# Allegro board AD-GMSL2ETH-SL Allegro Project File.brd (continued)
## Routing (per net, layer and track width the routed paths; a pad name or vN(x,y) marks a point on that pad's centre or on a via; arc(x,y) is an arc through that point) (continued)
UNNAMED_17_ADMAX2520X_I70_COMP: length 2
  TOP w0.254: U10.6 R102.1
UNNAMED_17_ADMAX2520X_I70_CS: length 16.7
  TOP w0.254: v1(28.68,85.22) 28.68,86.2 28.93,86.45 U10.10
  BOTTOM w0.254: R108.2 35.56,74.68 C230.1
  BOTTOM w0.305: v1(28.68,85.22) 28.68,84.05 35.26,77.48 35.26,76.2 35.7,75.76 C230.1
UNNAMED_17_ADMAX2520X_I70_DH: length 13.2
  TOP w0.305: U10.17 33.93,86.95 v2(34.32,86.56)
  TOP w0.406: v2(45.17,85.57) R106.1
  BOTTOM w0.406: v2(45.17,85.57) 44.18,86.56 v2(34.32,86.56)
UNNAMED_17_ADMAX2520X_I70_DL: length 14.8
  TOP w0.305: U10.15 v1(32.2,84.63)
  TOP w0.406: R107.1 v1(38.02,73.79)
  BOTTOM w0.406: v1(38.02,73.79) 38.02,76.71 32.2,82.53 v1(32.2,84.63)
UNNAMED_17_ADMAX2520X_I70_FB: length 3.5
  TOP w0.254: R112.2 R110.1 R237.1 U10.8
UNNAMED_17_ADMAX2520X_I70_FOSC: length 4.2
  TOP w0.254: R99.1 27.42,90.38 30.32,90.38 30.7,90 U10.4
UNNAMED_17_ADMAX2520X_I70_FSYNC: length 3.6
  TOP w0.254: U10.3 31.2,90.18 31.03,90.36 R93.2 R94.1 R95.1
UNNAMED_17_ADMAX2520X_I70_LX: length 14
  BOTTOM w0.508: v1(45.21,81.58) 41.25,85.55 v1(34.42,85.55) 33.57,85.55 C229.2
UNNAMED_17_ADMAX2520X_I70_OUT: length 17.6
  TOP w0.254: U10.9 28.69,86.95 27.94,86.2 v1(27.94,85.22)
  BOTTOM w0.254: R111.2 34.24,74.68 C230.2
  BOTTOM w0.305: v1(27.94,85.22) 27.94,83.75 34.54,77.14 34.54,76.2 34.1,75.76 C230.2
UNNAMED_17_ADMAX2520X_I70_PGOOD: length 3.5
  TOP w0.254: R249.2 27.86,89.48 28.32,89.95 29.95,89.95 30.2,89.7 U10.5
UNNAMED_17_ADMAX2520X_I70_SPS: length 2.6
  TOP w0.254: R96.2 R97.1 32.36,90.34 32.2,90.19 U10.1
UNNAMED_17_ADMAX17573_I106_BST: length 1.6
  TOP w0.305: U21.22 36.23,53.82 C247.2
UNNAMED_17_ADMAX17573_I106_MODE: length 3.6
  TOP w0.305: R241.1 R240.1 40.91,51.1 R239.1 39.59,51.1 39.25,50.76 U21.15
UNNAMED_17_ADMAX17573_I106_RESETN: length 1.8
  TOP w0.305: v1(39.18,50.02) 38.94,50.26 U21.14
  BOTTOM w0.483: R250.2 38.66,50.02 v1(39.18,50.02)
UNNAMED_17_ADMAX17573_I106_RT: length 2.1
  TOP w0.305: R238.1 39.19,53.34 38.61,52.76 U21.19
UNNAMED_17_ADMAX17573_I106_SS: length 2.6
  TOP w0.305: C248.1 39.83,52.2 38.89,51.26 U21.16
UNNAMED_17_CAP_I8_N1: length 11.2
  BOTTOM w0.762: P11.1 13.91,107.35 ; P11.1 13.91,104.55 ; P11.1 15.31,105.95 ; P11.1 12.51,105.95 ; 18.03,105.95 P11.4 ; P11.4 19.42,104.55 ; P11.4 20.82,105.95 ; P11.4 19.42,107.35
UNNAMED_17_CAP_I8_N2: length 11.2
  BOTTOM w0.762: 13.91,112.94 P11.3 ; P11.3 12.51,114.33 ; P11.3 15.31,114.33 ; P11.3 13.91,115.73 ; P11.6 19.42,115.73 ; P11.6 18.03,114.33 ; P11.6 19.42,112.94 ; P11.6 20.82,114.33
UNNAMED_17_CAP_I66_N1: length 0.9
  TOP w0.254: R102.2 24.84,88.45
UNNAMED_17_IND_I90_N2: length 2.2
  TOP w0.254: R109.1 v1(35.56,71.7)
  BOTTOM w0.254: v1(35.56,71.7) R108.1
UNNAMED_17_RES_I48_N2: length 9.6
  TOP w0.559: S12.2 45.44,111.4 R141.2
UNNAMED_17_RES_I79_N2: length 1.7
  TOP w0.406: Q7.4 44.72,83.96 44.27,84.41 R106.2
UNNAMED_17_RES_I83_N2: length 1.8
  TOP w0.406: R107.2 38.89,72.27 39.23,72.61 Q5.4
USB_DEBUG_N: length 6.1
  BOTTOM w0.127: U23.7 81.56,9.32 81.73,9.15 81.73,7.6 81.55,7.43 D4.C 81.55,6.85 81.71,6.69 81.71,5.06 81.55,4.9 P10.2
USB_DEBUG_P: length 6.1
  BOTTOM w0.127: U23.6 82.21,9.31 82.05,9.15 82.05,7.59 82.21,7.43 D5.C 82.21,6.85 82.04,6.67 82.04,5.06 82.2,4.9 P10.3
VCAM_9V0: length 12.3
  TOP w0.508: 135.28,96.91 135.28,96.91 R195.1 ; 135.28,96.91 135.86,97.5 v1(135.86,97.54) ; 135.28,96.91 R196.1 ; v1(146.65,101.57) 146.63,101.59 R198.1 ; R197.1 v1(146.56,92.52)
  TOP w0.762: v1(146.84,24.77) 146.62,24.55 R232.1 ; R233.1 v1(134.97,17.05) ; R234.1 v1(135.08,23.28) ; R235.1 v1(147.01,14.5)
  vias: v1(45.69,63.23) v1(45.69,62.47) v1(46.45,63.23) v1(46.45,62.47) v1(135.52,21.24) v1(135.5,20.4) v1(135.86,98.3)

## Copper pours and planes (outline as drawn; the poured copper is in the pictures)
1V2 on TOP: 94.06,24.68 94.06,21.32 94.33,21.04 96.09,21.04 96.23,21.18 96.23,22.17 95.64,22.76 95.64,24.62 95.39,24.87 94.25,24.87
1V2 on BOTTOM: 109.7,42.24 109.04,42.9 109.04,44.09 105.93,47.2 105.93,47.56 106.53,48.16 106.89,48.16 110.36,44.68 110.36,42.9
1V2 on BOTTOM: 107.8,89.54 109.22,88.11 109.22,86.87 109.7,86.39 110.36,87.05 110.36,88.67 108.6,90.44 109.07,90.91 107.9,92.08 107.82,92.08 106.54,90.79 106.54,90.38 107.39,89.54
1V2 on BOTTOM: 28.73,38.76 28.73,37.72 28.5,37.49 26.44,37.49 26.21,37.72 26.21,41.84 28.12,41.84 28.12,39.37
1V2 on BOTTOM: 110.34,72.69 111.05,71.98 109.59,70.52 108.79,71.32 110.16,72.69
1V2 on BOTTOM: 109.96,28.45 110.67,27.74 109.21,26.28 108.41,27.08 109.78,28.45
1V2 on L3_SIG: 94.11,23.62 95.15,23.62 95.58,24.05 95.58,29.97 95.4,30.15 93.9,30.15 93.9,23.83
1V2 on L5_PWR: 23.85,39.04 92.48,39.04 92.48,76.73 106.64,90.9 112.75,90.9 112.75,64.14 122.58,64.14 122.58,53.7 116.69,53.7 116.69,25.63 109.93,18.87 60.86,18.87 51.84,27.89 23.85,27.89 ; 2 cut-outs
1V8 on TOP: 50.11,96.95 50.11,94.92 48.26,94.92 48.01,95.17 48.01,96.7 48.26,96.95
1V8 on TOP: 118.69,94.69 118.69,92.91 116.76,92.91 116.46,93.22 116.46,94.36 116.79,94.69
1V8 on BOTTOM: 46.51,38.76 46.51,37.72 46.28,37.49 44.22,37.49 43.99,37.72 43.99,41.84 45.9,41.84 45.9,39.37
1V8 on L6_PWR: 133.98,96.47 113.59,96.47 110.69,99.36 98.09,99.36 95.43,102.03 46.23,102.03 46.23,84.29 106.03,84.29 106.03,38.94 44.96,38.94 44.96,17.55 55.6,6.91 58.65,6.91 61.26,9.53 133.98,9.53 133.98,46.3 140.21,52.53 140.21,90.25 ; 3 cut-outs
3V3 on BOTTOM (solid shape): 19.23,39.37 19.84,38.76 19.84,37.72 19.61,37.49 17.55,37.49 17.32,37.72 17.32,41.84 19.23,41.84
3V3 on TOP: 142.75,96.88 144.6,96.88 145.52,97.79 146.76,97.79 146.76,96.14 142.93,96.14 142.75,96.32
3V3 on TOP: 142.52,19.81 144.37,19.81 145.29,20.73 146.53,20.73 146.53,19.08 142.7,19.08 142.52,19.25
3V3 on BOTTOM: 47.12,27.28 47.12,23.04 51.38,23.04 51.38,27.28
3V3 on L5_PWR: 23.72,99.38 23.72,65.91 19.63,61.82 19.63,54.48 18.77,53.62 18.77,40.18 19.91,39.04 23.34,39.04 23.34,27.38 51.61,27.38 60.63,18.36 110.13,18.36 117.2,25.43 117.2,53.19 123.09,53.19 123.09,64.64 113.26,64.64 113.26,98.48 90.37,98.48 87.25,101.6 76.73,101.6 76.73,107.82 62.37,107.82 62.37,117.91 147.9,117.91 147.9,2.08 2.08,2.08 2.08,99.38
3V8 on TOP: 119.74,118.29 119.74,115.6 119.1,114.96 119.1,113.74 120.27,113.74 121.82,115.29 121.82,118.31 121.62,118.52 119.96,118.52
3V8 on BOTTOM: 37.62,38.76 37.62,37.72 37.39,37.49 35.33,37.49 35.1,37.72 35.1,41.84 37.01,41.84 37.01,39.37
3V8 on L6_PWR: 133.65,117.91 133.65,111.68 69.22,111.68 69.22,102.54 45.72,102.54 45.72,84.29 37.59,76.16 37.59,35.94 2.08,35.94 2.08,117.91 119.38,117.91 119.76,118.29 121.95,118.29 122.33,117.91
5V on BOTTOM (solid shape): 17.06,47.62 17.06,45.37 17.15,45.29 20.73,45.29 20.88,45.14 20.88,44.07 20.74,43.93 15.52,43.93 15.52,44.88 15.52,44.93 15.52,47.62 15.69,47.8 16.89,47.8
5V on TOP: 104.7,92.35 105.9,92.35 106.11,92.56 106.11,93.4 106.62,93.91 110.46,93.91 110.7,94.15 110.7,95.29 110.46,95.53 108.76,95.53 108.25,96.04 106.05,96.04 105.86,96.22 105.31,96.22 105.31,95.77 105.31,95.77 104.7,95.16 104.7,94.81 105.31,94.2 105.31,93.24 104.7,92.63
5V on TOP: 34.32,77.5 34.32,72.16 34.59,71.88 34.59,69.06 33.02,69.06 31.39,70.69 31.39,77.5
5V on BOTTOM: 24.41,43.93 29.63,43.93 29.77,44.07 29.77,45.14 29.62,45.29 26.04,45.29 25.95,45.37 25.95,47.62 25.78,47.8 24.58,47.8 24.41,47.62
5V on BOTTOM: 42.19,43.93 47.28,43.93 47.45,44.09 47.45,45.09 47.24,45.29 43.82,45.29 43.73,45.37 43.73,47.62 43.56,47.8 42.36,47.8 42.19,47.62
5V on BOTTOM: 33.3,43.93 38.52,43.93 38.66,44.07 38.66,45.14 38.51,45.29 34.93,45.29 34.84,45.37 34.84,47.62 34.67,47.8 33.47,47.8 33.3,47.62
5V on BOTTOM: 107.87,98.1 107.87,94.28 108.17,93.99 110.5,93.99 110.74,94.23 110.74,95.27 110.51,95.49 109.98,95.49 109.65,95.82 109.65,98.1
5V on L5_PWR: 24.23,99.38 24.23,65.71 20.17,61.65 20.17,54.28 19.28,53.39 19.28,39.55 58.39,39.55 58.39,77.24 92.02,77.24 106.45,91.67 112.75,91.67 112.75,97.97 90.14,97.97 87.12,100.99 76.02,100.99 76.02,107.11 51.39,107.11 43.65,99.38 ; 1 cut-out
5V_BIAS on L6_PWR: 33.93,93.8 33.93,91.06 31.27,88.39 31.27,84.35 24.69,84.35 24.69,93.8
9V_FB on TOP: 44.07,60.91 44.07,59.11 44.32,58.85 45.29,58.85 45.54,59.11 45.54,60.91 45.29,61.16 44.32,61.16
GND on TOP: 149.24,3 148.58,1.42 147,0.76 3,0.76 1.42,1.42 0.76,3 0.76,117 1.42,118.58 3,119.24 147,119.24 148.58,118.58 149.24,117 ; 31 cut-outs
GND on BOTTOM: 149.24,3 148.58,1.42 147,0.76 3,0.76 1.42,1.42 0.76,3 0.76,117 1.42,118.58 3,119.24 147,119.24 148.58,118.58 149.24,117 ; 26 cut-outs
GND on L2_GND, L4_GND, L7_GND, L9_GND: 149.24,3 148.58,1.42 147,0.76 3,0.76 1.42,1.42 0.76,3 0.76,117 1.42,118.58 3,119.24 147,119.24 148.58,118.58 149.24,117
GND on L3_SIG: 149.24,3 148.58,1.42 147,0.76 3,0.76 1.42,1.42 0.76,3 0.76,117 1.42,118.58 3,119.24 147,119.24 148.58,118.58 149.24,117 ; 19 cut-outs
GND on L5_PWR, L6_PWR: 147.97,3 147.68,2.32 147,2.03 3,2.03 2.32,2.32 2.03,3 2.03,117 2.32,117.68 3,117.97 147,117.97 147.68,117.68 147.97,117
GND on L8_SIG: 149.24,3 148.58,1.42 147,0.76 3,0.76 1.42,1.42 0.76,3 0.76,117 1.42,118.58 3,119.24 147,119.24 148.58,118.58 149.24,117 ; 13 cut-outs
VCC_IN on TOP: 30.28,110.95 30.28,107.77 29.9,107.39 27.25,107.39 27.25,101.9 30.71,101.9 33.81,98.81 33.81,88.14 32.69,88.14 32.69,87.78 34.77,87.78 36.37,86.18 36.37,78.69 43.33,78.69 43.33,92.48 38.43,92.48 37.59,93.32 37.59,104.39 34.42,107.57 31.39,107.57 30.66,108.31 30.66,110.95
VCC_IN on TOP: 34.67,50.9 34.67,49.2 36.35,49.2 36.35,47.45 36.17,47.27 34.06,47.27 32.56,48.77 28.42,48.77 28.17,49.02 28.17,52.02 28.42,52.27 32.89,52.27 32.89,51.46 33.45,50.9
VCC_IN on L5_PWR: 35.16,89.13 35.16,58.14 28.22,51.21 28.22,47.17 39.53,47.17 41.51,49.15 41.51,89.13
VCC_IN_1 on TOP: 29.62,110.95 29.62,108.03 27.89,108.03 27.89,108.97 26.06,108.97 26.06,110.79 26.21,110.95
VCC_IN_1 on TOP: 16.48,95 19.68,95 22,97.31 22,109.22 23.72,110.95 26.49,110.95 26.49,101.78 25.35,100.63 25.35,94.64 22.63,91.92 16.48,91.92
VDD_ANALOG on TOP: 118.69,95 118.69,99.14 116.79,99.14 116.46,98.81 116.46,97.56 116.99,97.03 116.99,95
VDD_ANALOG on L6_PWR: 69.72,102.54 69.72,111.18 133.68,111.18 133.68,96.98 113.79,96.98 110.9,99.87 98.27,99.87 95.61,102.54
(no net) on BOTTOM: 15.52,43.93 20.74,43.93 20.88,44.07 20.88,45.14 20.73,45.29 17.15,45.29 17.06,45.37 17.06,47.62 16.89,47.8 15.69,47.8 15.52,47.62
(no net) on BOTTOM: 15.44,43.72 19.12,43.72 19.12,42.5 17.32,42.5 17.32,42.73 17.06,42.99 15.44,42.99
(no net) on BOTTOM: 19.84,38.76 19.84,37.72 19.61,37.49 17.55,37.49 17.32,37.72 17.32,41.84 19.23,41.84 19.23,39.37
(no net) on BOTTOM: 33.22,43.72 36.9,43.72 36.9,42.5 35.1,42.5 35.1,42.73 34.84,42.99 33.22,42.99
(no net) on BOTTOM: 24.33,43.72 28.01,43.72 28.01,42.5 26.21,42.5 26.21,42.73 25.95,42.99 24.33,42.99
(no net) on BOTTOM: 42.11,43.72 45.79,43.72 45.79,42.5 43.99,42.5 43.99,42.73 43.73,42.99 42.11,42.99
A_VTERM on BOTTOM: 109.62,77.67 108.94,76.99 108.94,75.77 108,74.83 109.85,72.97 110.59,72.97 111.32,72.25 111.91,72.85 111.91,74.19 109.45,76.66 109.45,77.04 109.85,77.44
B_VTERM on BOTTOM: 109.62,33.55 108.74,32.66 108.74,31.57 107.72,30.56 109.55,28.73 110.21,28.73 110.93,28 111.35,28.42 111.35,30.61 109.47,32.49 109.47,32.92 109.86,33.31
EN_5V0 on TOP: 33.5,111.1 33.5,110.34 34.39,110.34 34.39,109.52 35.46,109.52 35.46,110.01 35.18,110.29 35.18,111.68 34.67,111.68 34.09,111.1
LDO_OUT on TOP: 37.08,49.2 37.08,48.16 37.24,48.01 40.84,48.01 41,48.16 41,49.61 39.45,49.61 39.04,49.2
LX1 on TOP: 34.67,52.63 33.73,52.63 33.4,52.96 33.4,60.25 33.66,60.5 35.1,60.5 35.1,55.02 35.86,54.25 35.86,53.31 34.67,53.31
UNNAMED_8_CN5P3SHLD_I32_N6 on BOTTOM: 87.27,2.79 87.27,0.76 75.13,0.76 75.13,2.79
UNNAMED_12_CN14P_I13_N2 on TOP: 50.8,96.95 50.8,94.82 51.21,94.41 51.21,91.59 54.89,91.59 55.17,91.87 55.17,94.23 52.45,96.95
UNNAMED_13_ADLTC330X_I1_SW1 on BOTTOM (solid shape): 28.01,42.5 26.21,42.5 26.21,42.73 25.95,42.99 24.33,42.99 24.33,43.72 28.01,43.72
UNNAMED_13_ADLTC330X_I31_SW1 on BOTTOM (solid shape): 45.79,42.5 43.99,42.5 43.99,42.73 43.73,42.99 42.11,42.99 42.11,43.72 45.79,43.72
UNNAMED_13_ADLTC330X_I33_SW1 on BOTTOM (solid shape): 19.12,42.5 17.32,42.5 17.32,42.73 17.06,42.99 15.44,42.99 15.44,43.72 19.12,43.72
UNNAMED_13_ADLTC330X_I92_SW1 on BOTTOM (solid shape): 36.9,42.5 35.1,42.5 35.1,42.73 34.84,42.99 33.22,42.99 33.22,43.72 36.9,43.72
UNNAMED_14_CN4P_I63_N4 on BOTTOM: 57.18,55.35 56.26,55.35 56.26,58.27 55.12,59.41 55.12,63.17 58.32,63.17 58.32,59.41 57.18,58.27
UNNAMED_15_CN2P_I75_N2 on TOP: 14.71,95 14.71,91.92 13.41,91.92 12.75,92.58 12.75,94.34 13.41,95
UNNAMED_17_ADLTC4355_I29_IN2 on TOP: 31.83,108.03 34.82,108.03 38.28,104.57 38.28,103.96 42.72,103.96 43.24,104.48 43.24,108.24 42.16,109.32 32.16,109.32 31.62,109.86 31.62,110.95 31.29,110.95 31.29,109.86 31.27,108.81 31.83,108.81
UNNAMED_17_ADLTC4355_I29_IN2 on BOTTOM: 37.67,109.3 37.67,106.78 38.59,106.78 38.59,104.49 39.02,104.06 42.57,104.06 43.13,104.62 43.13,108.71 42.55,109.3
UNNAMED_17_ADMAX2520X_I70_LX on TOP: 44.2,82.42 44.2,77.83 40.89,77.83 40.89,71.91 41.45,71.35 41.45,67.64 45.52,67.64 45.52,82.42
UNNAMED_17_ADMAX2520X_I70_LX on TOP: 32.59,86.59 32.59,85.27 32.79,85.06 35.26,85.06 35.26,85.7 34.37,86.59
UNNAMED_17_CAP_I8_N1 on BOTTOM: 12.45,107.76 20.62,107.76 21.56,108.7 21.56,109.78 27.35,109.78 27.81,109.31 27.81,104 27.33,103.52 12.42,103.52 11.71,104.23 11.71,107.03
UNNAMED_17_CAP_I8_N2 on BOTTOM: 12.45,112.52 20.62,112.52 21.56,111.58 21.56,110.44 27.28,110.44 27.81,110.97 27.81,116.28 27.33,116.76 12.42,116.76 11.71,116.05 11.71,113.26
UNNAMED_17_IND_I90_N2 on TOP: 40.08,71.35 40.08,67.64 36.58,67.64 35.2,69.01 35.2,71.35
VCAM_9V0 on TOP: 139.23,21.33 139.23,20.03 135.29,20.03 135.04,20.29 135.04,21.43 135.27,21.66 137.66,21.66 137.99,21.33
VCAM_9V0 on TOP: 139.45,98.37 139.45,97.08 135.51,97.08 135.32,97.27 135.32,98.54 135.48,98.7 137.87,98.7 138.2,98.37
VCAM_9V0 on TOP: 35.99,63.93 46.84,63.93 47.09,63.68 47.09,62.08 46.84,61.82 38.28,61.82 37.34,60.88 37.34,56.97 37.08,56.72 35.74,56.72 35.74,63.68
VCAM_9V0 on L6_PWR: 38.1,63.75 38.1,2.08 147.9,2.08 147.9,117.91 134.21,117.91 134.21,96.98 140.72,90.47 140.72,52.3 134.49,46.08 134.49,9.02 52.78,9.02 44.45,17.35 44.45,41.12 53.7,50.37 53.7,63.75 ; 1 cut-out

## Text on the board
Ref Des/Silkscreen Bottom: C | A
User.Comments: 6.    SMOOTHEN EDGES AND FREE FROM BURRS AFTER DEPANELIZATION. | 4.    RoHS COMPLIANCE: ASSEMBLY VENDOR SHOULD ASSURE COMPLIANCE | 5.    BOARDS TO BE SHIPPED SINGULATED AFTER ASSEMBLY PROCESS. | WITH LEAD-FREE AND RoHS PCB ASSEMBLY STANDARDS (EU RoHS | DIRECTIVE 2002/95/EC).
Ref Des/Assembly Top: MATE ENTRY | 1
Ref Des/Silkscreen Top: C | FAN_5V | REF_CLK_IN | PPS_IN | PS_SRST_B | PS_ERR_OUT | PS_POR_L | 1 | REF_CLK_OUT_N | MODE_0 | PS_ERR_ST | 2 | 3 | REF_CLK_OUT_P | A | (12V TO 48V_MAX) | JTAG | PGOOD | 5V | B | GMSL TO 10 GBIT ETH BOARD | DC_IN | ON | OFF
PAGE_OUTLINE: V.ARMADO | 14FEB24 | 25AUG23 | B | ECR-117940 | C.CARBUNARU | CUSTOMER EVAL BOARD Z
DIMENSION: FAB NOTES REVISION: 2ND NOVEMBER 2022 | 8.   IMPEDANCE REQUIREMENTS: IF NO STACKUP IS DEFINED, THE VENDOR IS ALLOWED TO ADJUST THE DIELECTRIC | 13.  PLATING SPECIFICATION: | 1.   DIMENSIONS ARE IN INCHES (EXCEPT WHERE NOTED). | ALL DOCUMENTS & SPECIFICATIONS REFERRED TO BELOW SHOULD BE THE LATEST REVISIONS. | 2.  BOARD MATERIAL:(USE CHECKED ITEMS) | 3.   ALL LAMINATES & BONDING MATERIALS SHOULD BE SELECTED FROM IPC-4101 OR IPC-4103,(TG>170 DEGC TD>300 DEGC) | 4.   REFER TO IPC-6010 SERIES, CLASS 2 FOR FABRICATION. | 5.   REFER TO LAMINATION DIAGRAM FOR OVERALL BOARD THICKNESS, TOLERANCE APPLIES AFTER ALL LAMINATION AND PLATING | 6.   BOW & TWIST NOT TO EXCEED 0.0075 INCHES (0.75%) PER LINEAR INCH AND SHOULD BE MEASURED PER IPC-TM-650, METHOD 2.4.22. | 7.   ACCEPTABILITY PER ADI SPECIFICATION TST00115. | 9.   FILLET OPTIONS TO ENHANCE RELIABILITY AT PAD JUNCTIONS WHERE SPACING PERMITS. | 10.  THIEVING: | 11.  LAYER TO LAYER REGISTRATION SHALL BE WITHIN 0.003 INCHES. | 12.  DRILL SIZES ARE FINISHED HOLE SIZES. ALL HOLES SHALL BE LOCATED WITHIN 0.005 INCHES DTP,UNLESS SPECIFIED. | 14.  SURFACE FINISH: | 15.  SOLDERMASK: | 16.  APPLY SILKSCREEN TO BOTH SIDES USING A NON-CONDUCTIVE, EPOXY BASED INK PER ARTWORK. | (X) WHITE | ( ) OTHER | PROCESSES. FINISHED THICKNESS MEASURED FROM TOP COPPER TO BOTTOM COPPER. | (X)  ISOLA 370HR OR S1000-2 OR IT180 OR EQUIVALENT | ( )  ISOLA-FR408HR OR EQUIVALENT | ( )  ISOLA IS410 | ( )  MEGTRON 6 | ( )  NELCO-4000-13 | ( )  ROGERS 4350B | ( ) ROGERS 3003 | ( ) ARLON 85N | ( ) EM370D | ( )  OTHER ________________________ | ( ) FILLETS ALLOWED | (X) FILLETS NOT ALLOWED | ( ) VENDOR MAY ADD THIEVING TO COMPENSATE FOR LOW COPPER DENSITY AREAS MAINTAINING A MINIMUM | (X) VENDOR MAY NOT ADD THIEVING TO COMPENSATE FOR LOW COPPER DENSITY AREAS. | (X) LPI | ( ) OTHER_________ | COLOR | (X) GREEN | HINDER PROPER SOLDER WICKING. BARREL RELIEF ON SOLDERMASK ALLOWED IN UNFILLED VIA IN PAD HOLES. | (X) REFER TO LAMINATION DIAGRAM FOR FINISHED COPPER WEIGHT/THICKNESS REQUIRMENTS | (X) IMMERSION GOLD (ENIG) 1.58-3.94 MICRO INCHES OVER 118-236 MICRO INCHES MIN. OF ELECTROLESS NICKEL PER IPC-4552 | ( ) OSP (ORGANIC SOLDERABILITY PRESERVATIVE) | ( ) IMMERSION SILVER | ( ) SOFT WIRE BONDABLE GOLD 30-50 MICRO INCHES OF SOFT WIRE | ( ) EDGE CONNECTOR FINGERS ARE TO BE PLATED WITH 100 MICRO-INCHES(.0001") OF LOW STRESS | THICKNESS & TRACE WIDTHS TO MEET THE IMPEDANCE REQUIREMENT. IF SPECIFIED, THE VENDOR MUST | TRACE WIDTH & SPACING THAT IMPACT THE REQUIREMENTS MUST HAVE WRITTEN APPROVAL FROM ADI. | MINIMUM BARREL PLATING OF 0.001 INCHES. PLATED HOLES SHALL NOT BE ROUGH OR IRREGULAR SO AS TO | SOLDERMASK OVER BARE COPPER OR BARE GOLD (BOTH SIDES) TO MEET IPC-SM-840. | IF PRESENT,DO NOT MODIFY SOLDERMASK DEFINED PADS (MASK OPENINGS LESS THAN COPPER PAD) WITHOUT APPROVAL. | MEET THE REQUIREMENTS LISTED IN THE IMPEDANCE TABLE. ANY ADJUSTMENT MADE TO THE DEFINED STACKUP, | UL FLAMMABILITY RATING 94V-0. BOARD MATERIAL & CONSTRUCTION SHALL MEET THE REQUIREMENTS OF UL796/UL796F. | BONDABLE GOLD OVER 100-150 MICRO INCHES OF NICKEL | NICKEL UNDER 30 MICRO-INCHES (.0003') OF GOLD | 0.100 INCH CLEARANCE FROM ALL COPPER FEATURES, | THE STARTING COPPER WEIGHT/THICKNESS CAN VARY AS LONG AS THE FINISHED COPPER | WEIGHT/THICKNESS IS NOT LESS THAN THE SPECIFIED VALUE. | UNLESS OTHERWISE SPECIFIED | HOMOGENOUS MATERIALS IN THIS BOARD SHALL BE COMPLAINT WITH THE EU DIRECTIVE 2002/95/EC | WORKMANSHIP SHALL CONFORM TO IPC-A-600, CLASS 2. | TRACE WIDTH/SPACE | - | 0.00500/0.00770 | 90 OHM | 21.  INTENTIONAL SHORTS: | 17.  FINAL ELECTRICAL TEST TO BE PERFORMED USING PROVIDED IPC-D-356A NETLIST OR ODB++ FORMAT FILE. | 22.  PEMNUTS: | 23.  MANUFACTURER TO ETCH/STAMP WITH PERMANENT NON-CONDUCTIVE INK | ON SECONDARY SIDE UNLESS OTHERWISE SPECIFIED: | 18.  A TIME DOMAIN REFLECTOMETER REPORT (TDR) FOR EACH IMPEDANCE CONTROLLED LAYER & A CERTIFICATE | 19.  IF PRESENT, ALL BLIND/BURIED VIAS WITH AN ASPECT RATIO <1:1 TO BE PLATED SHUT WITH COPPER WHEN | 20.  FOR VIA FILL INFORMATION REFER TO DRILL CHART: | 25. PANELIZATION: | 27.  MINIMUM DESIGN LINE WIDTH IS .00375 INCH. | 28.  MINIMUM DESIGN LINE SPACING IS .0035 INCH. | IS ACCEPTABLE, ALL OTHER INSTANCES MUST BE REPORTED. | IF AN INTENTIONAL SHORT REPORT IS SUPPLIED AND DOES NOT MATCH THE FAB DATA THEN | THE PCB SHALL HAVE A VERIFICATION STAMP. | (X)  NON-CONDUCTIVE EPOXY FILL ALL 0.006, 0.008 AND 0.010 INCHES DRILLED VIAS | ( )  COPPER FILL ALL 0.XXXX INCHES DRILLED VIAS | ( ) PEMNUTS TO BE INSTALLED BY FABRICATOR | ( ) PEMNUTS NOT TO BE INSTALLED BY FABRICATOR | (X) NOT APPLICABLE | USED AS VIA-IN-PAD OR AS A STACKED VIA. BLIND/BURIED VIAS WITH AN ASPECT RATIO >1:1 TO BE FILLED | A. UL CODE-FLAMMABILITY RATING FOR THOSE APPROVED MATERIALS(IF APPLICABLE) | B. DATE CODE | C. LOT NUMBER | D. MANUFACTURER LOGO | BOARDS TO BE SHIPPED IN ARRAY AND KEPT INTACT | PANEL TO BE SUBJECTED TO CUSTOMERS APPROVAL | PANEL SOLDER PASTE STENCIL GERBER TO BE PROVIDED TO ANALOG | CAN'T BE PERFORMED BECAUSE THE TRACE LENGTH IS TOO SHORT ON THE OUTER LAYERS AT THE PIN ESCAPES | ADI APPROVAL IS REQUIRED. | OF COMPLIANCE SHALL BE PROVIDED BY VENDOR AT TIME OF SHIPMENT. INSTANCES WHERE TDR TESTING | WITH NON-CONDUCTIVE EPOXY. | "" | (REF) | (4 PLACES) | SEE DETAIL 20 | NOTES: | TOOLING: | FINISH: | MATERIAL: | TESTING: | MISCELLANEOUS:
BODY_CENTER: LABEL PLACEMENT INFORMATION | HALF SIZE LABELS ARE | AVAILABLE IN THE LIBRARY | PLACE WHEELIE BIN LOGO | TO SUIT THE LAYOUT. | PLACE ROHS COMPLIANT LOGO | TO SUIT THE LAYOUT OR | DELETE IF NOT REQ'D. | PLACE CHINA ROHS COMPLIANT | LOGO TO SUIT THE LAYOUT OR | 1.THE BOARD SIZE CAN BE ADJUSTED TO SUIT THE APPLICATION. | 2.THE MOUNTING HOLES CAN BE MOVED/REMOVED TO SUIT THE APPLICATION. | 3.THE FIDUCIALS CAN BE MOVED TO SUIT THE APPLICATION. | 4.ADJUST THE DIMENSIONS TO SUIT THE APPLICATION. | 5.ADD THE CORRECT LAYER STACKUP ON FAB2 BASED ON THE NO OF LAYERS ON THE PCB. | 6.THE ROHS COMPLIANT AND WHEELIE BIN LOGO'S CAN BE MOVED TO THE DESIRED LOCATION. | HALF SIZE VERSIONS OF THE LABELS ARE AVAILABLE IN THE LIBRARY. | NOTES FOR TEMPLATE USAGE. | GENERIC D-SIZE TEMPLATE BR-067706A
User.11: C | A
User.12: C | A | DETAIL A | SEE DETAIL A
User.22: L2 GND | 08-      -07
User.23: L3 SIGNAL | 08-      -08
User.24: 08-      -09 | L4 GND
User.25: 08-      -10 | L5 POWER
User.26: L6 POWER | 08-      -11
User.27: 08-      -12 | L7 GND
User.28: 08-      -13 | L8 SIGNAL
User.29: L9 GND | 08-      -14
User.45: 2 | 5 | 4 | 3 | BLIND VIA L1 TO L3 | BURRIED VIA (L3-L8) | SEE DETAIL 19 | FIGURE | SIZE | 8.0 | BURIED VIA L8 TO L9 | DRILL CHART: L8_SIG to L9_GND | FINISHED HOLES IN MILS | PLATED | BLIND VIA L9 TO L10 | DRILL CHART: L9_GND to BOTTOM | BURIED VIA L2 TO L3 | DRILL CHART: L2_GND to L3_SIG | BLIND VIA L1 TO L2 | QTY | 32 | DRILL CHART: TOP to L2_GND | 46 | 38 | 90 | TOLERANCE/NOTES | 6.0 | 10.0 | 26.0 | 35.0 | 40.0 | 45.0 | 55.0 | 60.0 | 63.0 | 70.0 | 37.0 | 49.0 | 61.0 | 118.0 | 125.0 | 34.0x26.0 | 51.0x24.0 | DRILL CHART: TOP to BOTTOM | NON-PLATED | 493 | 1423 | 8 | 1 | 17 | 28 | 9
